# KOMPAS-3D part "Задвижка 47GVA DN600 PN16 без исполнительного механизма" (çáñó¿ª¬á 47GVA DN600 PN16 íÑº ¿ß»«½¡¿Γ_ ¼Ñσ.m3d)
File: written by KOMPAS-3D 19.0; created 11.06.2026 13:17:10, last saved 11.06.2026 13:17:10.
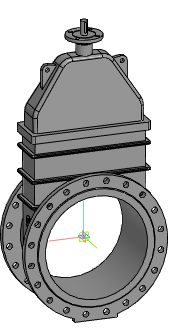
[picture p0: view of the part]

Document properties: Автор: Евгений; Полное имя файла: Z:\3.Личные\kachalov\001_3d для проектировщиков\2.2 Тип 47GVA, 47GVA.Z\_stp\_stp_Задвижка 47GVA DN40-DN1000 без исп.мех\Задвижка 47GVA DN600 PN16 без исполнит_ мех.m3d

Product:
- Part/product: Задвижка 47GVA DN600 PN16 без исполнительного механизма

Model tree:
1. Операция без истории:1  (labels: Задвижка 47GVA DN600 PN16 без исполнительного механизма)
